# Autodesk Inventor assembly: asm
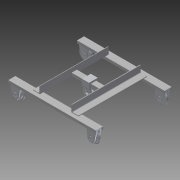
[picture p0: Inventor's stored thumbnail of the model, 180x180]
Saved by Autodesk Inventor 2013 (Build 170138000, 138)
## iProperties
Created: 2009-11
Part Number: asm
Document SubType Name: Assembly
Designer: pokornp
Mass: 1.57077e+06 g
Surface Area: 310738 cm^2
Volume: 253828 cm^3
Density: 6.18831 g/cm^3
_SolveAssemblyDoc: Frame Generator Solve Assembly
_Version: 15.0.0
Author: pokornp
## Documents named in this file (4)
- C:\Users\boganb\Documents\B2 Design\Goodyear\2013 Tutorial Files\Frame Analysis 1\analyze_frame.iam
- C:\Users\boganb\Documents\B2 Design\Goodyear\2013 Tutorial Files\Frame Analysis 1\chart.iam
- C:\Users\boganb\Documents\B2 Design\Goodyear\2013 Tutorial Files\Frame Analysis 1\sub.ipt
- C:\Users\boganb\Documents\B2 Design\Goodyear\2013 Tutorial Files\Frame Analysis 1\asm\Frame\Frame0001.iam
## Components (3 placed, 3 different names)
1. chart:1 [sub-assembly] — Tangent:1, Mate:1, Tangent:2, Mate:2
2. sub:1
3. Frame0001:1 [sub-assembly] — Tangent:1, Mate:1, Tangent:2, Mate:2
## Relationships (4: Tangent 2, Mate 2)
- Tangent:1: chart:1 ↔ Frame0001:1
- Mate:1: chart:1 ↔ Frame0001:1
- Tangent:2: chart:1 ↔ Frame0001:1
- Mate:2: chart:1 ↔ Frame0001:1
